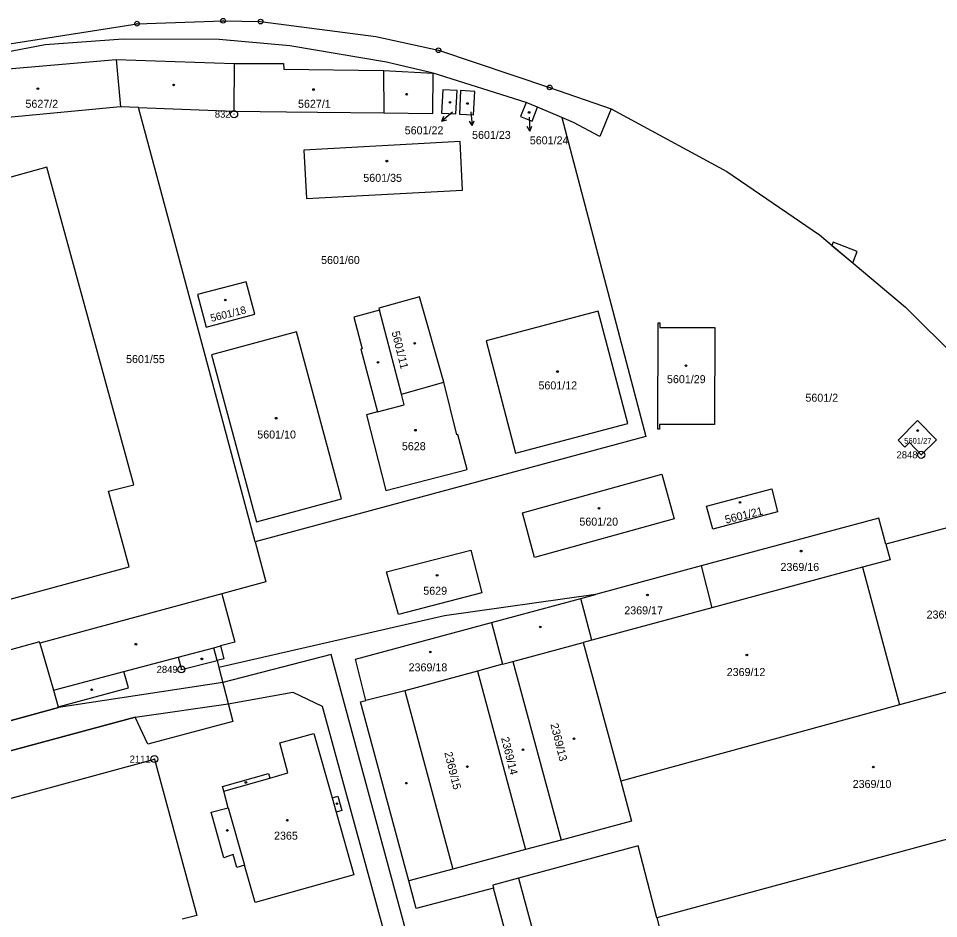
# Model space of a CAD drawing. Extents: x -821458 to -820266, y -1071458 to -1069826.
# Drawn here: x -821186.2 to -820990.7, y -1070338.6 to -1070147.2 of the extents above; entities that cross this region are included whole.
import ezdxf

# ---------------------------------------------------------------- set-up
doc = ezdxf.new("R2010")
doc.units = 0
for name, color, linetype in [('Vrstva 1', 7, 'Continuous'), ('Vrstva 13', 7, 'Continuous'), ('Vrstva 2', 7, 'Continuous'), ('Vrstva 4', 7, 'Continuous'), ('Vrstva 5', 7, 'Continuous'), ('Vrstva 7', 7, 'Continuous'), ('Vrstva 8', 7, 'Continuous')]:
    doc.layers.add(name, color=color, linetype=linetype)

msp = doc.modelspace()

# ---------------------------------------------------------------- linework, layer by layer
at = {"layer": 'Vrstva 1'}
for p, q in [((-821165.45, -1070155.95), (-821164.54, -1070166.03)), ((-821078.33, -1070165.11), (-821098.1, -1070158.83)), ((-821075.91, -1070166.06), (-821078.33, -1070165.11)), ((-821164.54, -1070166.03), (-821196.49, -1070169.04)), ((-821160.69, -1070166.17), (-821164.54, -1070166.03)), ((-821070.73, -1070168.3), (-821075.91, -1070166.06)), ((-821041.15, -1070263.6), (-821063.59, -1070269.66)), ((-821041.15, -1070263.6), (-821038.86, -1070272.49)), ((-821006.88, -1070263.86), (-821038.86, -1070272.49)), ((-821006.88, -1070263.86), (-820998.99, -1070293.15)), ((-821085.66, -1070275.61), (-821066.68, -1070270.49)), ((-821066.68, -1070270.49), (-821063.59, -1070269.66)), ((-821064.39, -1070279.38), (-821066.68, -1070270.49)), ((-821038.86, -1070272.49), (-821064.39, -1070279.38)), ((-821085.66, -1070275.61), (-821083.37, -1070284.5)), ((-821143.99, -1070283.71), (-821143.62, -1070285.15)), ((-821083.37, -1070284.5), (-821088.68, -1070285.94)), ((-821088.68, -1070285.94), (-821078.44, -1070323.89)), ((-820970.82, -1070285.44), (-820998.99, -1070293.15)), ((-820998.99, -1070293.15), (-821058.23, -1070309.37)), ((-820978.59, -1070318.91), (-821050.57, -1070338.41)), ((-821070.91, -1070321.87), (-821078.44, -1070323.89)), ((-821079.93, -1070329.99), (-821052.32, -1070432.3)), ((-821050.57, -1070338.41), (-821028.04, -1070425.85))]:
    msp.add_line(p, q, dxfattribs=at)
for points in [[(-821424.05, -1070234.93), (-821417.57, -1070231.43), (-821414.51, -1070229.78), (-821410.24, -1070227.71), (-821394.03, -1070220.21), (-821378.02, -1070213.44), (-821369.48, -1070209.59), (-821355.16, -1070203.21), (-821343.71, -1070197.56), (-821334.74, -1070193.15), (-821322.52, -1070188.21), (-821304.53, -1070182.89), (-821261.01, -1070170.88), (-821261.33, -1070168.93), (-821259.98, -1070168.07), (-821228.39, -1070159.48), (-821216.2, -1070157.01), (-821161.01, -1070148.33), (-821142.72, -1070147.71), (-821134.77, -1070147.89), (-821110.29, -1070151.09), (-821096.97, -1070153.98), (-821073.33, -1070161.88), (-821060.28, -1070166.43)], [(-821098.1, -1070158.83), (-821108, -1070156.52), (-821128.56, -1070153.06), (-821143.55, -1070151.69), (-821163.95, -1070151.61), (-821180.55, -1070152.81), (-821224.5, -1070161.24), (-821227.59, -1070162.16)], [(-821196.49, -1070169.04), (-821197.43, -1070158.72), (-821165.45, -1070155.95)], [(-821165.45, -1070155.95), (-821140.36, -1070156.81), (-821129.86, -1070156.83), (-821129.85, -1070158.03), (-821108.61, -1070158.27), (-821098.1, -1070158.83)], [(-821160.69, -1070166.17), (-821140.43, -1070166.93), (-821129.26, -1070167.05), (-821122.63, -1070167.12), (-821108.55, -1070167.27), (-821098.15, -1070167.39), (-821098.1, -1070158.83)], [(-821096.03, -1070162.37), (-821096.3, -1070167.37), (-821093.26, -1070167.53), (-821093, -1070162.53), (-821096.03, -1070162.37)], [(-821092.25, -1070162.57), (-821092.52, -1070167.57), (-821089.51, -1070167.73), (-821089.24, -1070162.74), (-821092.25, -1070162.57)], [(-821078.33, -1070165.11), (-821079.53, -1070168.08), (-821077.08, -1070169.04), (-821075.91, -1070166.06)], [(-821135.89, -1070258.47), (-821146.48, -1070219.06), (-821160.69, -1070166.17)], [(-821060.28, -1070166.43), (-821062.65, -1070172.3), (-821068.26, -1070169.37), (-821070.73, -1070168.3)], [(-821060.28, -1070166.43), (-821035.7, -1070179.73), (-821016.02, -1070193.21), (-820997.71, -1070208.62), (-820986.52, -1070219.72), (-820975.99, -1070231.76), (-820966.49, -1070244.53), (-820961.88, -1070251.33), (-820959.73, -1070254.91)], [(-821070.73, -1070168.3), (-821052.89, -1070236.05), (-821135.89, -1070258.47)], [(-821125.56, -1070175.19), (-821125, -1070185.51), (-821091.82, -1070183.72), (-821092.38, -1070173.39), (-821125.56, -1070175.19)], [(-821231.96, -1070211.82), (-821208.34, -1070205.39), (-821203.45, -1070223.23), (-821207.26, -1070224.26), (-821206.7, -1070226.16), (-821210.65, -1070227.31), (-821197.92, -1070273.36), (-821162.69, -1070263.76), (-821167.08, -1070247.71), (-821161.7, -1070246.35), (-821180.15, -1070178.8), (-821207.52, -1070186.43), (-821207.22, -1070187.44), (-821236.44, -1070195.36)], [(-821148.17, -1070205.88), (-821146.32, -1070212.82), (-821136, -1070210.06), (-821137.83, -1070203.21), (-821148.17, -1070205.88)], [(-821095.81, -1070224.51), (-821100.98, -1070206.42), (-821109.6, -1070208.83), (-821109.49, -1070209.25), (-821114.95, -1070210.69), (-821113.17, -1070217.46), (-821113.48, -1070217.54), (-821109.89, -1070230.84)], [(-821056.71, -1070233.33), (-821063, -1070209.44), (-821086.85, -1070215.72), (-821080.56, -1070239.61), (-821056.71, -1070233.33)], [(-821038.22, -1070212.93), (-821038.29, -1070233.56), (-821049.98, -1070233.51), (-821050, -1070234.51), (-821050.33, -1070234.52), (-821050.26, -1070211.89), (-821049.93, -1070211.9), (-821049.94, -1070212.89), (-821038.22, -1070212.93)], [(-821117.58, -1070249.35), (-821127.11, -1070213.87), (-821145.16, -1070218.71), (-821135.62, -1070254.2), (-821117.58, -1070249.35)], [(-821109.89, -1070230.84), (-821112.26, -1070231.46), (-821108.16, -1070247.59), (-821090.89, -1070243.13), (-821092.86, -1070235.63), (-821093.07, -1070235.71), (-821095.81, -1070224.51)], [(-821109.89, -1070230.84), (-821104.21, -1070229.35), (-821104.8, -1070227.09), (-821095.81, -1070224.51)], [(-820995.15, -1070232.68), (-820991.13, -1070236.82), (-820994.37, -1070239.98), (-820996.87, -1070237.37), (-820997.84, -1070238.33), (-820999.26, -1070236.86), (-820995.15, -1070232.68)], [(-821049.48, -1070244.11), (-821046.85, -1070253.56), (-821076.58, -1070261.77), (-821079.11, -1070252.34), (-821049.48, -1070244.11)], [(-821040.02, -1070250.86), (-821026.15, -1070247.18), (-821024.9, -1070252.11), (-821038.68, -1070255.76), (-821040.02, -1070250.86)], [(-821001.88, -1070258.94), (-821003.37, -1070253.41), (-821041.15, -1070263.6)], [(-820983.06, -1070258.22), (-820987.52, -1070255.14), (-821001.88, -1070258.94)], [(-821135.89, -1070258.47), (-821133.61, -1070266.95), (-821143, -1070269.5)], [(-821001.88, -1070258.94), (-821000.98, -1070262.27), (-821006.88, -1070263.86)], [(-821107.98, -1070264.86), (-821090.11, -1070260.24), (-821087.76, -1070269.34), (-821105.45, -1070273.94), (-821107.98, -1070264.86)], [(-821143, -1070269.5), (-821181.65, -1070279.98), (-821181.7, -1070279.74), (-821202.58, -1070285.44)], [(-821143, -1070269.5), (-821140.2, -1070279.83), (-821143.27, -1070280.59), (-821142.55, -1070283.35), (-821143.99, -1070283.71)], [(-821063.59, -1070269.66), (-821095.66, -1070274.21), (-821143.62, -1070285.15)], [(-821112.37, -1070292.17), (-821114.62, -1070283.43), (-821085.66, -1070275.61)], [(-821064.39, -1070279.38), (-821066.18, -1070279.87), (-821058.23, -1070309.37)], [(-821201.2, -1070300.13), (-821177.68, -1070293.69), (-821177.75, -1070293.52), (-821162.8, -1070289.53), (-821163.81, -1070286.05), (-821152.29, -1070282.97), (-821151.59, -1070285.59), (-821143.99, -1070283.71)], [(-821083.37, -1070284.5), (-821081.14, -1070283.9), (-821070.91, -1070321.87)], [(-821143.62, -1070285.15), (-821140.63, -1070296.64), (-821158.7, -1070301.47), (-821161.41, -1070295.73), (-821238.1, -1070316.46)], [(-821088.68, -1070285.94), (-821104.12, -1070290.11), (-821112.37, -1070292.17)], [(-821103.26, -1070330.55), (-821113.53, -1070292.47), (-821112.37, -1070292.17)], [(-821130.69, -1070301.18), (-821123.42, -1070299.18), (-821119.56, -1070312.86), (-821118.35, -1070312.52), (-821117.48, -1070315.6), (-821118.69, -1070315.94), (-821114.95, -1070329.29), (-821135.93, -1070335.16), (-821138.15, -1070327.22), (-821139.81, -1070327.68), (-821140.59, -1070324.92), (-821142.6, -1070325.62), (-821145.28, -1070315.97), (-821141.61, -1070314.99), (-821142.6, -1070311.49), (-821142.87, -1070310.51), (-821133.05, -1070307.71), (-821132.77, -1070308.69), (-821128.99, -1070307.61), (-821130.69, -1070301.18)], [(-821258.12, -1070332.09), (-821157.32, -1070304.65), (-821148.28, -1070337.88), (-821151.41, -1070338.71)], [(-821058.23, -1070309.37), (-821055.94, -1070317.85), (-821070.91, -1070321.87)], [(-821078.44, -1070323.89), (-821093.89, -1070328.04), (-821103.26, -1070330.55)], [(-821050.57, -1070338.41), (-821054.52, -1070323.09), (-821079.93, -1070329.99)], [(-821079.93, -1070329.99), (-821085.4, -1070331.47), (-821085.24, -1070332.07)], [(-821085.24, -1070332.07), (-821101.67, -1070336.44), (-821103.26, -1070330.55)], [(-821052.32, -1070432.3), (-821069.44, -1070436.81), (-821092.97, -1070349.27), (-821081.42, -1070346.17), (-821085.24, -1070332.07)]]:
    msp.add_lwpolyline(points, dxfattribs=at)
at = {"layer": 'Vrstva 13'}
msp.add_lwpolyline([(-821013.36, -1070195.45), (-821008.93, -1070199.18), (-821007.97, -1070196.73), (-821013.09, -1070194.76)], close=True, dxfattribs=at)
for points in [[(-820997.43, -1070556.41), (-821006.07, -1070524.66), (-821005.9, -1070515.7), (-821028.94, -1070431.25), (-821033.52, -1070432.51), (-821068.02, -1070441.99), (-821073.83, -1070437.98), (-821076.8, -1070427.13), (-821081.99, -1070424.41), (-821083.77, -1070418.28), (-821089.59, -1070394.16), (-821098.28, -1070361.81), (-821119.79, -1070282.42), (-821142.78, -1070288.39), (-821177.68, -1070293.69), (-821201.2, -1070300.13)], [(-821238.1, -1070316.46), (-821161.41, -1070295.73), (-821141.61, -1070292.88), (-821127.93, -1070290.42), (-821121.69, -1070293.38), (-821101.69, -1070366.43), (-821093.68, -1070395.87), (-821082.52, -1070436.8), (-821072.94, -1070449.98), (-821065.02, -1070479.68), (-821061.41, -1070488.13), (-821057.64, -1070503.1), (-821056.19, -1070506.57), (-821048.26, -1070536.22), (-821044.69, -1070535.25), (-821045.15, -1070533.58), (-821011.58, -1070524.4), (-821001.61, -1070561.6)]]:
    msp.add_lwpolyline(points, dxfattribs=at)
at = {"layer": 'Vrstva 4'}
for p, q in [((-821140.36, -1070156.81), (-821140.43, -1070166.93)), ((-821108.61, -1070158.27), (-821108.55, -1070167.27)), ((-821104.8, -1070227.09), (-821109.49, -1070209.25)), ((-821181.65, -1070279.98), (-821178.75, -1070289.98)), ((-821152.29, -1070282.97), (-821144.7, -1070280.97)), ((-821144.7, -1070280.97), (-821143.27, -1070280.59)), ((-821143.99, -1070283.71), (-821144.7, -1070280.97)), ((-821081.14, -1070283.9), (-821066.18, -1070279.87)), ((-821178.75, -1070289.98), (-821163.81, -1070286.05)), ((-821178.75, -1070289.98), (-821177.75, -1070293.52)), ((-821104.12, -1070290.11), (-821093.89, -1070328.04)), ((-821142.6, -1070311.49), (-821132.77, -1070308.69)), ((-821119.56, -1070312.86), (-821118.69, -1070315.94)), ((-821141.61, -1070314.99), (-821138.15, -1070327.22))]:
    msp.add_line(p, q, dxfattribs=at)
at = {"layer": 'Vrstva 5'}
for centre in [(-821153.24, -1070161.35), (-821182.08, -1070162.14), (-821123.51, -1070162.34), (-821103.71, -1070163.32), (-821094.52, -1070165.06), (-821090.8, -1070165.3), (-821077.69, -1070167.2), (-821107.92, -1070177.55), (-821142.26, -1070207.08), (-821102.03, -1070216.27), (-821109.82, -1070220.33), (-821071.67, -1070222.27), (-821044.36, -1070221.04), (-821131.45, -1070232.19), (-821101.85, -1070234.74), (-820995.13, -1070234.81), (-821062.86, -1070251.32), (-821032.9, -1070250.1), (-821019.89, -1070260.45), (-821097.24, -1070265.58), (-821052.55, -1070269.77), (-821075.32, -1070276.57), (-821161.25, -1070280.23), (-821098.7, -1070281.89), (-821031.42, -1070282.52), (-821147.23, -1070283.35), (-821170.66, -1070289.92), (-821068.15, -1070300.34), (-821079, -1070302.68), (-821090.82, -1070306.25), (-821004.56, -1070306.35), (-821137.88, -1070309.62), (-821103.77, -1070309.77), (-821118.5, -1070314.13), (-821129.06, -1070317.65), (-821141.82, -1070319.83)]:
    msp.add_circle(centre, 0.175, dxfattribs=at)
at = {"layer": 'Vrstva 7'}
for p, q in [((-821093.99, -1070167.13), (-821096.24, -1070169.02)), ((-821090.06, -1070167.07), (-821089.8, -1070170)), ((-821096.24, -1070169.02), (-821095.81, -1070168.01)), ((-821096.24, -1070169.02), (-821095.18, -1070168.77)), ((-821089.8, -1070170), (-821090.38, -1070169.06)), ((-821089.8, -1070170), (-821089.4, -1070168.98)), ((-821077.7, -1070168.19), (-821077.55, -1070171.16)), ((-821077.55, -1070171.16), (-821078.09, -1070170.19)), ((-821077.55, -1070171.16), (-821077.1, -1070170.14))]:
    msp.add_line(p, q, dxfattribs=at)
at = {"layer": 'Vrstva 8'}
for centre, radius in [((-821161.01, -1070148.33), 0.5), ((-821142.72, -1070147.71), 0.5), ((-821142.72, -1070147.71), 0.0303), ((-821134.77, -1070147.89), 0.5), ((-821134.77, -1070147.89), 0.0303), ((-821161.01, -1070148.33), 0.0303), ((-821096.97, -1070153.98), 0.5), ((-821096.97, -1070153.98), 0.0303), ((-821073.33, -1070161.88), 0.5), ((-821073.33, -1070161.88), 0.0303), ((-821140.38, -1070167.57), 0.75), ((-821140.38, -1070167.57), 0.03), ((-820994.37, -1070239.98), 0.75), ((-820994.37, -1070239.98), 0.03), ((-821151.59, -1070285.59), 0.75), ((-821151.59, -1070285.59), 0.03), ((-821157.32, -1070304.65), 0.75), ((-821157.32, -1070304.65), 0.03)]:
    msp.add_circle(centre, radius, dxfattribs=at)

# ---------------------------------------------------------------- texts
at = {"layer": 'Vrstva 2'}
for s, height, p in [('5627/2', 1.7, (-821184.72, -1070166.21)), ('5627/1', 1.7, (-821126.8, -1070166.21)), ('5601/22', 1.7, (-821104.13, -1070171.85)), ('5601/23', 1.7, (-821089.82, -1070172.83)), ('5601/24', 1.7, (-821077.55, -1070173.98)), ('5601/35', 1.7, (-821112.93, -1070181.95)), ('5601/60', 1.7, (-821121.9, -1070199.42)), ('5601/55', 1.7, (-821163.34, -1070220.48)), ('5601/12', 1.7, (-821075.71, -1070226.07)), ('5601/29', 1.7, (-821048.4, -1070224.75)), ('5601/2', 1.7, (-821018.98, -1070228.69)), ('5601/10', 1.7, (-821135.46, -1070236.51)), ('5628', 1.7, (-821104.73, -1070238.99)), ('5601/27', 1.2, (-820997.99, -1070237.6)), ('5601/20', 1.7, (-821067.01, -1070255.03)), ('2369/16', 1.7, (-821024.28, -1070264.66)), ('5629', 1.7, (-821100.18, -1070269.72)), ('2369/17', 1.7, (-821057.47, -1070273.89)), ('2369/11', 1.7, (-820993.23, -1070274.78)), ('2369/18', 1.7, (-821103.3, -1070286)), ('2369/12', 1.7, (-821035.71, -1070287)), ('2369/10', 1.7, (-821008.94, -1070310.79)), ('2365', 1.7, (-821131.9, -1070321.78))]:
    msp.add_text(s, height=height, dxfattribs=at).set_placement(p)
for s, height, rotation, p in [('5601/18', 1.6, 14, (-821145.2, -1070211.74)), ('5601/11', 1.7, 284, (-821106.93, -1070213.9)), ('5601/21', 1.7, 14, (-821035.85, -1070254.63)), ('2369/13', 1.7, 284, (-821073.18, -1070297.27)), ('2369/14', 1.7, 284, (-821083.67, -1070300.18)), ('2369/15', 1.7, 284, (-821095.73, -1070303.3))]:
    msp.add_text(s, height=height, rotation=rotation, dxfattribs=at).set_placement(p)
at = {"layer": 'Vrstva 8'}
for s, p in [('832', (-821144.48, -1070168.32)), ('2848', (-820999.62, -1070240.73)), ('2849', (-821156.84, -1070286.34)), ('2111', (-821162.57, -1070305.4))]:
    msp.add_text(s, height=1.5, dxfattribs=at).set_placement(p)

doc.saveas('drawing.dxf')
